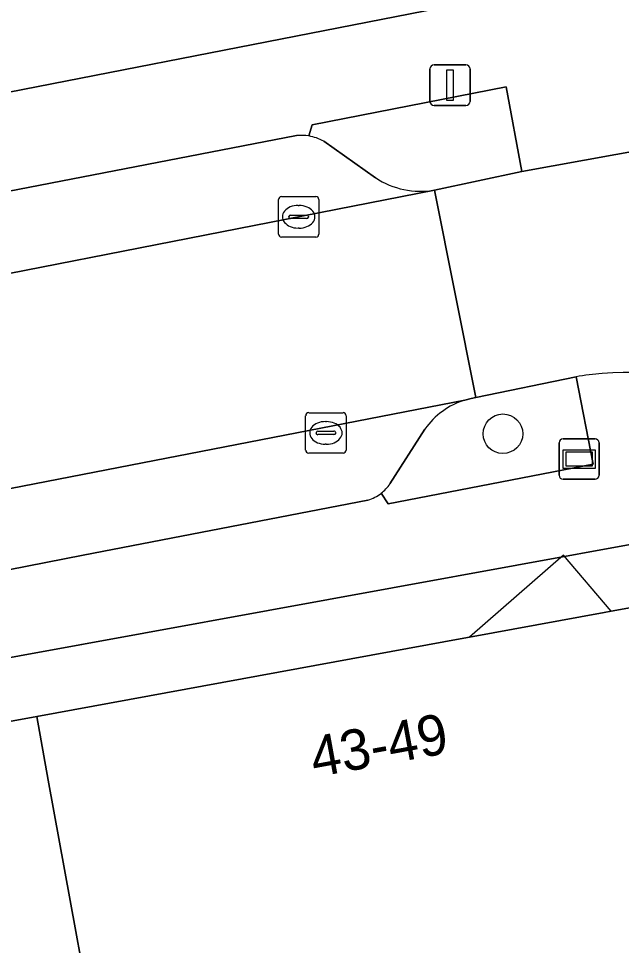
# Model space of a CAD drawing. Extents: x 160377 to 161131, y 383938 to 384853.
# Drawn here: x 160732.96 to 160747.87, y 384495.91 to 384518.82 of the extents above; entities that cross this region are included whole.
import ezdxf

# ---------------------------------------------------------------- set-up
doc = ezdxf.new("R2010")
doc.units = 0
for name, color, linetype in [('IMGEO_Boom', 7, 'Continuous'), ('IMGEO_Erf', 7, 'Continuous'), ('IMGEO_Groenvoorziening', 7, 'Continuous'), ('IMGEO_Kolk', 7, 'Continuous'), ('IMGEO_Lichtmast', 7, 'Continuous'), ('IMGEO_Pand', 7, 'Continuous'), ('IMGEO_Pand_nummerreeks', 7, 'Continuous'), ('IMGEO_Pand_overbouw', 7, 'Continuous'), ('IMGEO_Parkeervlak_open', 7, 'Continuous'), ('IMGEO_Rijbaan_lokaal_open', 7, 'Continuous'), ('IMGEO_Straatnaambord', 7, 'Continuous'), ('IMGEO_Voetpad_open', 7, 'Continuous')]:
    doc.layers.add(name, color=color, linetype=linetype)

msp = doc.modelspace()

# ---------------------------------------------------------------- linework, layer by layer
at = {"layer": 'IMGEO_Boom'}
msp.add_circle((160744.939, 384508.558), 0.489, dxfattribs=at)
at = {"layer": 'IMGEO_Erf'}
for points in [[(160742.043, 384557.929), (160741.675, 384559.771), (160712.316, 384578.736), (160711.06, 384579.547), (160690.284, 384592.968), (160678.608, 384600.475), (160670.645, 384605.594), (160652.047, 384589.687), (160648.865, 384586.974), (160652.625, 384581.692), (160662.829, 384567.417), (160665.29, 384560.709), (160670.064, 384547.52), (160670.583, 384546.086), (160681.057, 384517.15), (160682.984, 384507.279), (160717.593, 384514.044), (160723.481, 384515.195), (160749.399, 384520.262)], [(160733.41, 384501.572), (160743.969, 384503.506), (160744.111, 384503.532), (160747.441, 384504.142), (160747.616, 384504.174), (160749.48, 384504.514), (160748.356, 384505.867), (160702.23, 384497.471), (160702.513, 384495.915), (160711.376, 384497.537), (160716.884, 384498.546), (160722.393, 384499.555), (160727.901, 384500.564)]]:
    msp.add_lwpolyline(points, close=True, dxfattribs=at)
at = {"layer": 'IMGEO_Groenvoorziening'}
for points in [[(160743.248, 384514.579), (160745.402, 384515.035), (160745.019, 384517.129), (160740.223, 384516.191), (160740.136, 384515.916)], [(160740.509, 384515.785), (160741.788, 384514.886)], [(160741.926, 384507.086), (160742.102, 384506.823), (160747.167, 384507.806), (160746.747, 384509.966)], [(160746.747, 384509.966), (160744.272, 384509.456), (160744.156, 384509.432), (160743.994, 384509.389)], [(160743.01, 384508.673), (160742.144, 384507.321)]]:
    msp.add_lwpolyline(points, dxfattribs=at)
for centre, radius, start, end in [((160739.953, 384514.799), 1.132, 60.5928, 80.704), ((160742.901, 384516.552), 2.003, 236.2616, 279.9888), ((160744.558, 384507.579), 1.896, 107.3213, 144.7611), ((160741.304, 384507.882), 1.01, 308.0186, 326.2798)]:
    msp.add_arc(centre, radius, start, end, dxfattribs=at)
at = {"layer": 'IMGEO_Kolk'}
for p, q in [((160739.461, 384514.42), (160740.313, 384514.42)), ((160739.386, 384513.494), (160739.386, 384514.346)), ((160739.874, 384514.2), (160739.899, 384514.2)), ((160740.387, 384514.346), (160740.387, 384513.494)), ((160739.645, 384513.914), (160739.645, 384513.926)), ((160739.688, 384513.963), (160740.086, 384513.963)), ((160740.129, 384513.926), (160740.129, 384513.914)), ((160740.083, 384513.877), (160739.685, 384513.877)), ((160739.897, 384513.64), (160739.872, 384513.64)), ((160740.313, 384513.42), (160739.461, 384513.42)), ((160740.06, 384508.153), (160740.06, 384509.005)), ((160740.135, 384509.079), (160740.987, 384509.079)), ((160740.548, 384508.859), (160740.573, 384508.859)), ((160741.061, 384509.005), (160741.061, 384508.153)), ((160740.319, 384508.573), (160740.319, 384508.585)), ((160740.757, 384508.536), (160740.359, 384508.536)), ((160740.362, 384508.622), (160740.76, 384508.622)), ((160740.803, 384508.585), (160740.803, 384508.573)), ((160740.571, 384508.299), (160740.546, 384508.299)), ((160740.987, 384508.079), (160740.135, 384508.079))]:
    msp.add_line(p, q, dxfattribs=at)
for points in [[(160739.461, 384514.42), (160740.313, 384514.42)], [(160739.386, 384513.494), (160739.386, 384514.346)], [(160740.387, 384514.346), (160740.387, 384513.494)], [(160740.313, 384513.42), (160739.461, 384513.42)], [(160740.06, 384508.153), (160740.06, 384509.005)], [(160740.135, 384509.079), (160740.987, 384509.079)], [(160741.061, 384509.005), (160741.061, 384508.153)], [(160740.987, 384508.079), (160740.135, 384508.079)]]:
    msp.add_lwpolyline(points, dxfattribs=at)
for centre, radius, start, end in [((160739.463, 384514.344), 0.0765, 91.552, 178.448), ((160739.463, 384514.344), 0.0765, 91.552, 178.448), ((160740.311, 384514.344), 0.0765, 1.552, 88.448), ((160740.311, 384514.344), 0.0765, 1.552, 88.448), ((160739.685, 384513.923), 0.0403, 85.8775, 175.7526), ((160739.682, 384513.913), 0.0366, 178.938, 274.7102), ((160740.086, 384513.92), 0.043, 264.8664, 352.4533), ((160740.09, 384513.925), 0.0386, 1.7309, 96.639), ((160739.463, 384513.496), 0.0765, 181.552, 268.448), ((160739.463, 384513.496), 0.0765, 181.552, 268.448), ((160740.311, 384513.496), 0.0765, 271.552, 358.448), ((160740.311, 384513.496), 0.0765, 271.552, 358.448), ((160740.137, 384509.003), 0.0765, 91.552, 178.448), ((160740.137, 384509.003), 0.0765, 91.552, 178.448), ((160740.985, 384509.003), 0.0765, 1.552, 88.448), ((160740.985, 384509.003), 0.0765, 1.552, 88.448), ((160740.359, 384508.582), 0.0403, 85.8775, 175.7526), ((160740.356, 384508.572), 0.0366, 178.938, 274.7102), ((160740.76, 384508.579), 0.043, 264.8664, 352.4533), ((160740.764, 384508.584), 0.0386, 1.7309, 96.639), ((160740.137, 384508.155), 0.0765, 181.552, 268.448), ((160740.137, 384508.155), 0.0765, 181.552, 268.448), ((160740.985, 384508.155), 0.0765, 271.552, 358.448), ((160740.985, 384508.155), 0.0765, 271.552, 358.448)]:
    msp.add_arc(centre, radius, start, end, dxfattribs=at)
for centre, major_axis, ratio, start_param, end_param in [((160739.873, 384513.92), (-0.387, 0.002), 0.722429, 4.712389, 7.853982), ((160739.898, 384513.92), (-0.39, 0.002), 0.717154, 1.570796, 4.712389), ((160740.547, 384508.579), (-0.387, 0.002), 0.722429, 4.712389, 7.853982), ((160740.572, 384508.579), (-0.39, 0.002), 0.717154, 1.570796, 4.712389)]:
    msp.add_ellipse(centre, major_axis=major_axis, ratio=ratio, start_param=start_param, end_param=end_param, dxfattribs=at)
at = {"layer": 'IMGEO_Lichtmast'}
for p, q in [((160743.134, 384516.772), (160743.134, 384517.572)), ((160743.134, 384517.572), (160743.134, 384516.772)), ((160743.234, 384517.672), (160744.024, 384517.672)), ((160744.024, 384517.672), (160743.234, 384517.672)), ((160744.124, 384517.572), (160744.124, 384516.772)), ((160744.124, 384516.772), (160744.124, 384517.572)), ((160744.024, 384516.672), (160743.234, 384516.672)), ((160743.234, 384516.672), (160744.024, 384516.672))]:
    msp.add_line(p, q, dxfattribs=at)
msp.add_lwpolyline([(160743.554, 384517.547), (160743.704, 384517.547), (160743.704, 384516.797), (160743.554, 384516.797), (160743.554, 384517.547)], dxfattribs=at)
for centre, start, end in [((160743.234, 384517.572), 90, 180), ((160743.234, 384517.572), 90, 180), ((160744.024, 384517.572), 0, 90), ((160744.024, 384517.572), 360, 90), ((160743.234, 384516.772), 180, 270), ((160743.234, 384516.772), 180, 270), ((160744.024, 384516.772), 270, 0), ((160744.024, 384516.772), 270, 0)]:
    msp.add_arc(centre, 0.1, start, end, dxfattribs=at)
at = {"layer": 'IMGEO_Pand'}
for points in [[(160749.48, 384504.514), (160747.616, 384504.174), (160747.441, 384504.142), (160744.111, 384503.532), (160743.969, 384503.506), (160733.41, 384501.572), (160733.696, 384500), (160735.181, 384491.847), (160744.603, 384493.576), (160748.367, 384489.058), (160755.275, 384494.766), (160753.833, 384496.492), (160755.214, 384497.645)], [(160735.181, 384491.847), (160733.696, 384500), (160733.41, 384501.572), (160727.901, 384500.564), (160728.004, 384500), (160729.673, 384490.836)]]:
    msp.add_lwpolyline(points, close=True, dxfattribs=at)
at = {"layer": 'IMGEO_Pand_overbouw'}
msp.add_lwpolyline([(160746.436, 384505.556), (160744.111, 384503.532), (160747.616, 384504.174)], close=True, dxfattribs=at)
at = {"layer": 'IMGEO_Parkeervlak_open'}
for points in [[(160739.835, 384515.926), (160728.974, 384513.831)], [(160741.788, 384514.886), (160740.509, 384515.785)], [(160726.323, 384511.268), (160725.821, 384511.164), (160743.248, 384514.579)], [(160743.994, 384509.389), (160686.58, 384498.232), (160686.513, 384498.219)], [(160742.144, 384507.321), (160743.01, 384508.673)], [(160724.13, 384503.516), (160723.832, 384505.141), (160725.475, 384505.483), (160725.782, 384503.839), (160734.561, 384505.557), (160741.599, 384506.921)]]:
    msp.add_lwpolyline(points, dxfattribs=at)
for centre, radius, start, end in [((160739.948, 384514.794), 1.138, 80.4901, 95.7043), ((160739.953, 384514.799), 1.132, 60.5928, 80.704), ((160742.901, 384516.552), 2.003, 236.2616, 279.9888), ((160744.558, 384507.579), 1.896, 107.3213, 144.7611), ((160741.304, 384507.882), 1.01, 308.0186, 326.2798), ((160741.328, 384507.865), 0.983, 286.0336, 307.5163)]:
    msp.add_arc(centre, radius, start, end, dxfattribs=at)
at = {"layer": 'IMGEO_Rijbaan_lokaal_open'}
msp.add_lwpolyline([(160764.851, 384513.492), (160765.465, 384513.637), (160764.445, 384518.726), (160763.616, 384518.568), (160758.22, 384517.505), (160754.212, 384516.716), (160749.281, 384515.741), (160745.402, 384515.035), (160743.248, 384514.579), (160744.272, 384509.456), (160746.747, 384509.966)], dxfattribs=at)
msp.add_lwpolyline([(160743.994, 384509.389), (160744.156, 384509.432), (160744.272, 384509.456), (160743.248, 384514.579), (160725.821, 384511.164), (160716.914, 384509.435), (160685.714, 384503.375), (160686.58, 384498.232)], close=True, dxfattribs=at)
for centre, radius, start, end in [((160747.944, 384503.019), 7.049, 94.4702, 99.7798), ((160748.005, 384502.594), 7.478, 32.6927, 94.6763)]:
    msp.add_arc(centre, radius, start, end, dxfattribs=at)
at = {"layer": 'IMGEO_Straatnaambord'}
for p, q in [((160746.426, 384508.433), (160747.216, 384508.433)), ((160747.216, 384508.433), (160746.426, 384508.433)), ((160746.326, 384507.533), (160746.326, 384508.333)), ((160746.326, 384508.333), (160746.326, 384507.533)), ((160747.316, 384508.333), (160747.316, 384507.533)), ((160747.316, 384507.533), (160747.316, 384508.333)), ((160747.216, 384507.433), (160746.426, 384507.433)), ((160746.426, 384507.433), (160747.216, 384507.433))]:
    msp.add_line(p, q, dxfattribs=at)
for points in [[(160746.427, 384508.165), (160747.215, 384508.165), (160747.215, 384507.701), (160746.427, 384507.701), (160746.427, 384508.165)], [(160746.492, 384508.1), (160746.492, 384507.766), (160747.15, 384507.766), (160747.15, 384508.1), (160746.492, 384508.1)]]:
    msp.add_lwpolyline(points, dxfattribs=at)
for centre, start, end in [((160746.426, 384508.333), 90, 180), ((160746.426, 384508.333), 90, 180), ((160747.216, 384508.333), 0, 90), ((160747.216, 384508.333), 360, 90), ((160746.426, 384507.533), 180, 270), ((160746.426, 384507.533), 180, 270), ((160747.216, 384507.533), 270, 0), ((160747.216, 384507.533), 270, 0)]:
    msp.add_arc(centre, 0.1, start, end, dxfattribs=at)
at = {"layer": 'IMGEO_Voetpad_open'}
for points in [[(160818.393, 384535.428), (160814.707, 384533.039), (160790.946, 384528.391), (160785.079, 384527.244), (160759.828, 384522.305), (160757.353, 384521.841), (160751.078, 384520.595), (160749.399, 384520.262), (160723.481, 384515.195), (160717.593, 384514.044), (160682.984, 384507.279), (160680.437, 384506.971), (160680.951, 384504.783), (160681.144, 384502.714), (160682.351, 384502.826), (160682.165, 384504.852), (160687.745, 384505.957), (160687.9, 384505.71)], [(160740.136, 384515.916), (160740.223, 384516.191), (160745.019, 384517.129), (160745.402, 384515.035), (160749.281, 384515.741), (160754.212, 384516.716), (160753.75, 384518.859), (160757.796, 384519.653), (160758.22, 384517.505), (160763.616, 384518.568), (160763.18, 384520.71), (160771.072, 384522.24), (160771.211, 384522.018)], [(160728.974, 384513.831), (160739.835, 384515.926)], [(160746.747, 384509.966), (160747.167, 384507.806), (160742.102, 384506.823), (160741.926, 384507.086)], [(160741.599, 384506.921), (160734.561, 384505.557), (160725.782, 384503.839), (160724.13, 384503.516), (160702.355, 384499.255), (160700.435, 384498.879), (160689.896, 384496.817)], [(160675.404, 384486.813), (160675.535, 384486.616), (160675.88, 384486.183), (160676.022, 384486.022), (160679.533, 384487.97), (160687.518, 384494.794), (160700.75, 384497.202), (160702.23, 384497.471), (160748.356, 384505.867)]]:
    msp.add_lwpolyline(points, dxfattribs=at)
for centre, radius, start, end in [((160739.948, 384514.794), 1.138, 80.4901, 95.7043), ((160747.944, 384503.019), 7.049, 94.4702, 99.7798), ((160748.005, 384502.594), 7.478, 32.6927, 94.6763), ((160741.328, 384507.865), 0.983, 286.0336, 307.5163)]:
    msp.add_arc(centre, radius, start, end, dxfattribs=at)

# ---------------------------------------------------------------- texts
at = {"layer": 'IMGEO_Pand_nummerreeks'}
msp.add_text('43-49', height=1, rotation=10.3992, dxfattribs=at).set_placement((160740.276, 384500.063))

doc.saveas('drawing.dxf')
